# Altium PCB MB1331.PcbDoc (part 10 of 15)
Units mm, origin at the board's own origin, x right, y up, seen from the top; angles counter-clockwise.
Board outline 169.25 x 173.25 mm, 6 copper layers (Top Layer, Signal Layer 1, Signal Layer 2, Signal Layer 3, Signal Layer 4, Bottom Layer), stack 1.556 mm thick; 871 components, 699 nets, 3244 pads, 2370 vias.
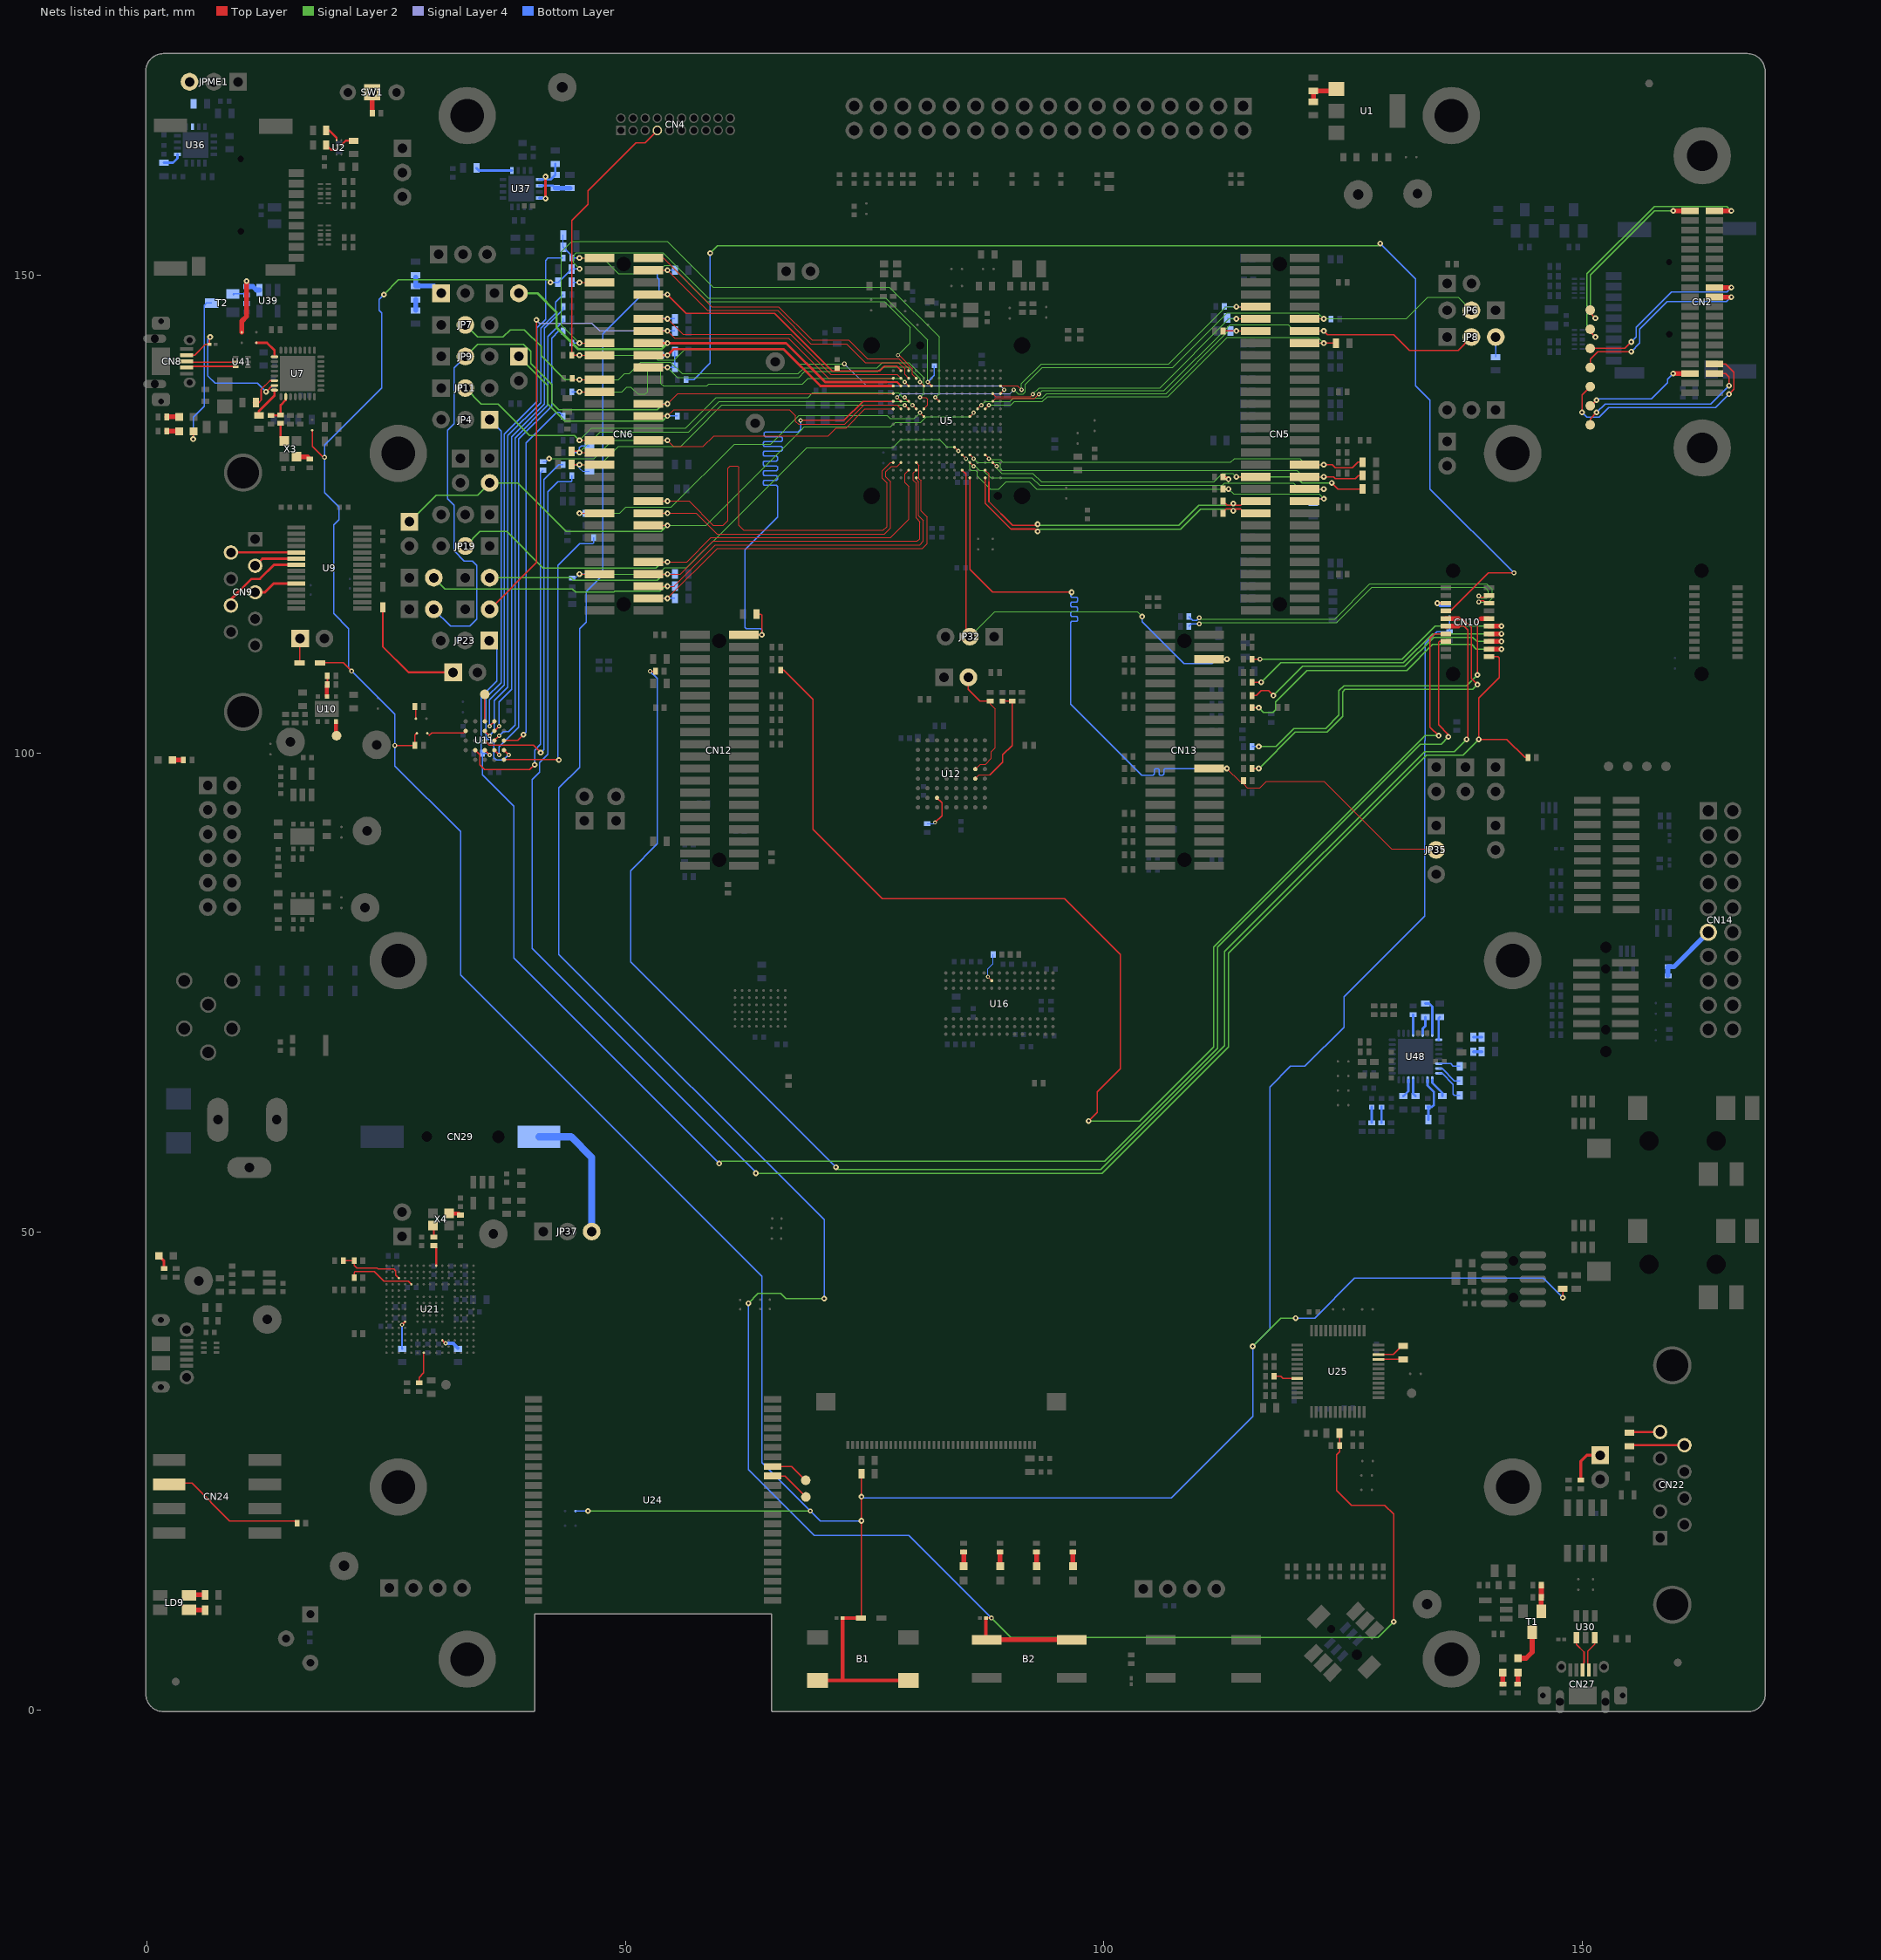
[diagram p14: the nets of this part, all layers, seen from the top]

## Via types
v1: diameter 0.6, hole 0.254, Top Layer to Bottom Layer, tented both sides, 1747 vias
v2: diameter 0.45, hole 0.2, Top Layer to Bottom Layer, tented both sides, 272 vias
v3: diameter 0.406, hole 0.203, Top Layer to Bottom Layer, tented both sides, 160 vias
v4: diameter 0.6, hole 0.25, Top Layer to Bottom Layer, tented both sides, 82 vias
v5: diameter 0.45, hole 0.25, Top Layer to Bottom Layer, tented both sides, 45 vias
v6: diameter 0.5, hole 0.25, Top Layer to Bottom Layer, tented both sides, 23 vias
v7: diameter 1.016, hole 0.508, Top Layer to Bottom Layer, tented both sides, 17 vias
v8: diameter 0.508, hole 0.254, Top Layer to Bottom Layer, tented both sides, 9 vias
v9: diameter 0.61, hole 0.305, Top Layer to Bottom Layer, tented both sides, 7 vias
v10: diameter 0.5, hole 0.254, Top Layer to Bottom Layer, tented both sides, 6 vias
v11: diameter 0.4, hole 0.2, Top Layer to Bottom Layer, tented both sides, 1 vias
v12: diameter 0.483, hole 0.254, Top Layer to Bottom Layer, tented both sides, 1 vias

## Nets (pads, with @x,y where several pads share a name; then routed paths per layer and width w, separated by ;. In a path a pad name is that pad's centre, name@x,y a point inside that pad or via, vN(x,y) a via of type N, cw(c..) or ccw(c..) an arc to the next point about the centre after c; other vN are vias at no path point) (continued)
NetC147_2: C147.2 U48.9 | length 2.4
  Bottom Layer w0.254: U48.9@135.013,70.076 135.013,72.337 C147.2@135.128,72.452
NetC148_1: C148.1 U48.8 | length 3.7
  Bottom Layer w0.254: C148.1@133.638,73.886 C148.1@133.604,73.852 134.019,73.852 134.338,73.533 U48.8@134.338,70.751
NetC148_2: C148.2 U48.6 | length 1.8
  Bottom Layer w0.254: U48.6@133.338,70.751 133.338,71.247 133.604,71.513 C148.2@133.604,72.452
NetC151_1: C151.1 R410.2 | length 0.9
  Bottom Layer w0.3: C151.1@138.622,70.358 R410.2@139.508,70.358
NetC159_1: C159.1 R412.2 | length 0.9
  Bottom Layer w0.3: C159.1@138.622,68.834 R412.2@139.508,68.834
NetC160_2: C160.2 U48.14 | length 2.3
  Bottom Layer w0.127: U48.14@135.013,67.576 136.259,67.576 136.525,67.31 C160.2@137.222,67.31
NetC161_2: C161.2 U48.15 | length 2.7
  Bottom Layer w0.127: U48.15@135.013,67.076 135.362,67.076 136.652,65.786 C161.2@137.222,65.786
NetC163_2: C163.2 U48.16 | length 3.8
  Bottom Layer w0.127: U48.16@135.013,66.576 135.354,66.576 136.525,65.405 136.525,64.389 136.652,64.262 C163.2@137.222,64.262
NetC164_2: C164.2 U48.17 | length 2.1
  Bottom Layer w0.254: U48.17@134.338,65.901 134.338,65.56 135.382,64.516 C164.2@135.382,64.2
NetC165_1: C165.1 U48.21 | length 1.8
  Bottom Layer w0.254: U48.21@132.338,65.901 132.338,64.45 C165.1@132.588,64.2
NetC166_1: C166.1 U48.22 | length 1.9
  Bottom Layer w0.254: C166.1@131.318,64.2 131.838,64.72 U48.22@131.838,65.901
NetC167_1: C167.1 R415.2 U48.18 | length 5
  Bottom Layer w0.254: U48.18@133.838,65.901 133.838,65.298 134.493,64.643 134.493,63.246 134.297,63.05 C167.1@133.858,63.05 133.92,62.988 R415.2@133.92,61.722
NetC169_1: C169.1 R417.2 | length 1.6
  Bottom Layer w0.254: R417.2@129.032,61.41 C169.1@129.032,63.05
NetC170_1: C170.1 R418.2 | length 1.6
  Bottom Layer w0.254: R418.2@128.016,61.41 C170.1@128.016,63.05
NetC187_2: C187.2 U21.F13 | length 2
  Top Layer w0.2: U21.F13@30.875,38.675 v2(31.2,38.35)
  Bottom Layer w0.381: v2(31.2,38.35) 32,38.35 C187.2@32.495,37.855
NetC188_2: C188.2 U21.M10 | length 3
  Top Layer w0.2: v2(26.65,40.3) U21.M10@26.975,40.625
  Bottom Layer w0.203: v2(26.65,40.3) 26.65,37.804 C188.2@26.67,37.784
NetCN2_1: CN2.1 TP2.1 | length 19
  Top Layer w0.127: TP2.1@150.846,146.327 150.846,146.016 v1(151.384,145.478)
  Top Layer w0.508: v1(159.513,156.685) CN2.1@161.28,156.685
  Signal Layer 2 w0.127: v1(151.384,145.478) 150.876,145.987 150.876,149.987 157.574,156.685 v1(159.513,156.685)
NetCN2_2: CN2.2 TP3.1 | length 28
  Top Layer w0.127: TP3.1@150.846,144.327 150.846,144.048 v1(151.384,143.51)
  Top Layer w0.508: CN2.2@163.83,156.685 v1(165.597,156.685)
  Signal Layer 2 w0.127: v1(151.384,143.51) 150.495,144.399 150.495,150.114 157.543,157.162 165.119,157.162 v1(165.597,156.685)
NetCN2_18: CN2.18 TP4.1 | length 19.7
  Top Layer w0.127: TP4.1@150.846,142.327 154.456,142.327 v1(155.13,143.002)
  Top Layer w0.508: CN2.18@163.83,148.685 v1(165.597,148.685)
  Bottom Layer w0.127: v1(155.13,143.002) 155.638,143.51 155.638,144.526 159.321,148.209 165.121,148.209 v1(165.597,148.685)
NetCN2_20: CN2.20 TP5.1 | length 20.9
  Top Layer w0.127: TP5.1@150.846,140.327 150.846,141.194 151.638,141.986 v1(155.13,141.986)
  Top Layer w0.508: CN2.20@163.83,147.685 v1(165.597,147.685)
  Bottom Layer w0.127: v1(155.13,141.986) 156.019,142.875 156.019,144.335 158.877,147.193 165.105,147.193 v1(165.597,147.685)
NetCN2_34: CN2.34 TP6.1 | length 24.5
  Top Layer w0.127: v1(149.987,135.636) 149.987,137.468 TP6.1@150.846,138.327 ; CN2.34@163.83,140.685 165.004,140.685 165.862,139.827 165.862,138.049 v1(165.354,137.541)
  Bottom Layer w0.127: v1(149.987,135.636) 150.495,135.128 151.765,135.128 152.781,136.144 163.957,136.144 v1(165.354,137.541)
NetCN2_35: CN2.35 TP7.1 | length 12
  Top Layer w0.127: TP7.1@150.846,136.327 150.932,136.327 v1(151.511,136.906)
  Top Layer w0.508: v1(159.512,139.685) CN2.35@161.28,139.685
  Bottom Layer w0.127: v1(151.511,136.906) 151.638,137.033 157.226,137.033 158.943,138.75 158.943,139.116 v1(159.512,139.685)
NetCN2_36: CN2.36 TP8.1 | length 19.1
  Top Layer w0.127: TP8.1@150.846,134.327 150.846,134.971 v1(151.511,135.636) ; CN2.36@163.83,139.685 164.988,139.685 165.354,139.319 v1(165.354,138.43)
  Bottom Layer w0.127: v1(151.511,135.636) 152.4,136.525 163.449,136.525 v1(165.354,138.43)
NetCN7_1: CN7.1 R221.2 R222.1 | length 4.1
  Bottom Layer w0.127: R221.2@28.08,149.774 R221.2@28.08,149.974
  Bottom Layer w0.5: R221.2@28.08,149.774 R222.1@28.08,148.834 29.982,148.834 CN7.1@30.734,148.082
NetCN8_2: CN8.2 U41.6 | length 5.2
  Top Layer w0.155: CN8.2@4.13,140.32 4.26,140.45 9.218,140.45 U41.6@9.256,140.412
NetCN8_3: CN8.3 U41.5 | length 5.2
  Top Layer w0.155: CN8.3@4.13,140.97 4.225,140.875 9.219,140.875 U41.5@9.256,140.912
NetCN8_4: CN8.4 U6.1 U7.23 | length 15.8
  Top Layer w0.155: CN8.4@4.13,141.62 4.968,141.62 6.096,142.748 U6.1@6.546,142.748 6.546,143.452 v1(6.604,143.51) ; v1(12.446,137.795) 13.101,138.45 U7.23@13.323,138.45
  Bottom Layer w0.155: v1(6.604,143.51) 6.35,143.256 6.35,139.446 7.112,138.684 11.557,138.684 v1(12.446,137.795)
NetCN9_2: CN9.2 U9.6 | length 5.1
  Top Layer w0.254: CN9.2@11.835,119.61 CN9.2@11.31,119.61 12.055,120.355 U9.6@15.6,120.355
NetCN9_3: CN9.3 U9.10 | length 4.7
  Top Layer w0.254: CN9.3@11.31,116.84 12.319,116.84 13.234,117.755 U9.10@15.6,117.755
NetCN9_6: CN9.6 U9.5 | length 6.8
  Top Layer w0.254: CN9.6@8.77,120.995 8.78,121.005 U9.5@15.6,121.005
NetCN9_8: CN9.8 U9.7 | length 9
  Top Layer w0.254: CN9.8@8.77,115.455 8.77,116.085 10.922,118.237 11.811,118.237 13.279,119.705 U9.7@15.6,119.705
NetCN14_11: CN14.11 R395.2 R396.1 | length 6.6
  Bottom Layer w0.508: R396.1@158.95,76.8 158.95,77.65 R395.2@159,77.7 159.58,77.7 CN14.11@163.195,81.315
NetCN22_5: CN22.5 R169.2 | length 3.2
  Top Layer w0.254: R169.2@154.94,29.018 155.018,29.096 CN22.5@158.155,29.096
NetCN22_9: CN22.9 R174.2 | length 5.8
  Top Layer w0.254: R174.2@154.94,27.624 155.027,27.711 CN22.9@160.695,27.711
NetCN24_5: CN24.5 R177.1 | length 15
  Top Layer w0.127: CN24.5@2.413,23.749 4.699,23.749 8.636,19.812 15.425,19.812 R177.1@15.679,19.558
NetCN27_2: CN27.2 U30.6 | length 3.7
  Top Layer w0.155: CN27.2@150.705,4.23 150.705,4.743 150.59,4.858 150.59,6.191 151.318,6.919 U30.6@151.318,7.588
NetCN27_3: CN27.3 U30.4 | length 3.7
  Top Layer w0.155: U30.4@149.418,7.588 149.418,6.887 150.209,6.096 150.209,4.972 150.055,4.818 CN27.3@150.055,4.23
NetCN29_1: CN29.1 JP37.3 | length 14.2
  Bottom Layer w0.762: CN29.1@40.966,59.944 44.323,59.944 46.482,57.785 JP37.3@46.482,50.038
NetD1_2: D1.2 JP22.1 | length 12.6
  Top Layer w0.2: D1.2@24.638,115.262 24.638,111.162 27.332,108.468 JP22.1@32.005,108.468
NetD2_2: D2.2 JP24.1 | length 2.6
  Top Layer w0.127: D2.2@15.948,109.474 15.948,111.96 JP24.1@16.002,112.014
NetJP38_1: JP38.1 R176.2 | length 4.3
  Top Layer w0.3: R176.2@149.86,24.072 149.86,26.035 150.495,26.67 JP38.1@151.892,26.67
NetJPME1_3: JPME1.3 R197.2 U36.6
NetLD1_2: LD1.2 R178.1 | length 1.5
  Top Layer w0.508: R178.1@85.344,16.568 85.36,16.552 LD1.2@85.36,15.082
NetLD2_2: LD2.2 R179.1 | length 1.5
  Top Layer w0.508: R179.1@89.154,16.568 89.17,16.552 LD2.2@89.17,15.082
NetLD3_2: LD3.2 R180.1 | length 1.5
  Top Layer w0.508: R180.1@92.964,16.568 92.98,16.552 LD3.2@92.98,15.082
NetLD4_2: LD4.2 R181.1 | length 1.5
  Top Layer w0.508: R181.1@96.774,16.568 96.774,15.098 LD4.2@96.79,15.082
NetLD5_1: LD5.1 R42.1 | length 1.3
  Top Layer w0.508: R42.1@2.065,135.165 LD5.1@3.365,135.165
NetLD6_1: LD6.1 R46.1 | length 1.3
  Top Layer w0.508: R46.1@2.065,133.665 LD6.1@3.365,133.665
NetLD6_2: LD6.2 T2.3 | length 16.1
  Top Layer w0.127: v1@4.865,132.881 LD6.2@4.865,133.665
  Bottom Layer w0.127: v1(4.826,132.842) 4.826,135.128 5.969,136.271 5.969,146.812 6.223,147.066 T2.3@6.774,147.066
NetLD7_1: LD7.1 R112.2 | length 1.2
  Top Layer w0.508: LD7.1@2.655,99.314 R112.2@3.81,99.314
NetLD8_1: LD8.1 R149.1 | length 1.5
  Top Layer w0.3: LD8.1@1.25,47.5 1.778,46.972 R149.1@1.778,46.17
NetLD9_2: LD9.2 R190.1 | length 1.7
  Top Layer w0.508: LD9.2@4.377,12.028 4.427,12.078 R190.1@6.077,12.078
NetLD9_3: LD9.3 R192.1 | length 1.7
  Top Layer w0.508: LD9.3@4.377,10.528 4.427,10.478 R192.1@6.077,10.478
NetLD10_1: LD10.1 R195.1 | length 1.2
  Top Layer w0.254: R195.1@141.697,2.771 R195.1@141.732,2.736
  Top Layer w0.508: R195.1@141.697,2.771 LD10.1@141.697,3.955
NetLD11_1: LD11.1 R196.1 | length 1.2
  Top Layer w0.254: R196.1@143.256,2.736 R196.1@143.297,2.777
  Top Layer w0.508: R196.1@143.297,2.777 LD11.1@143.297,3.955
NetLD11_2: LD11.2 T1.3 | length 3.8
  Top Layer w0.508: LD11.2@143.297,5.455 144.139,5.455 144.78,6.096 T1.3@144.78,8.171
NetR1_2: R1.2 R2.2 U1.1 | length 3.6
  Top Layer w0.508: R2.2@121.92,168.086 R1.2@121.92,169.226 124.127,169.226 U1.1@124.333,169.432
NetR3_2: R3.2 SW1.1 | length 2.2
  Top Layer w0.508: SW1.1@23.538,169.075 23.55,169.063 R3.2@23.55,166.9
NetR4_2: R4.2 U2.1 | length 1.7
  Top Layer w0.203: R4.2@18.734,165.1 19.05,165.1 19.816,164.334 U2.1@19.816,164.072
NetR5_1: R5.1 U2.7 | length 1.5
  Top Layer w0.203: U2.7@20.316,163.572 20.766,164.022 R5.1@21.59,164.022
NetR6_2: R6.2 U2.3 | length 1.3
  Top Layer w0.203: R6.2@18.734,163.576 19.238,163.072 U2.3@19.816,163.072
NetR36_1: R36.1 U7.22 | length 3.8
  Top Layer w0.152: R36.1@11.114,136.652 R36.1@11.368,136.652 11.684,136.652 11.938,136.906 11.938,138.049 12.839,138.95 U7.22@13.323,138.95
NetR37_1: R37.1 U7.24 | length 3.5
  Top Layer w0.254: R37.1@11.684,135.32 11.684,135.763 13.323,137.402 U7.24@13.323,137.95 U7.24@13.109,137.95
NetR38_1: R38.1 X3.3 | length 2
  Top Layer w0.254: R38.1@13.97,134.482 13.97,133.042 X3.3@14.361,132.651
NetR38_2: R38.2 R39.2 U7.26 | length 3.2
  Top Layer w0.254: R39.2@12.954,135.324 13.912,135.324 R38.2@13.97,135.382 13.97,136.398 14.498,136.926 U7.26@14.498,137.275
NetR52_2: R52.2 X3.1 | length 1.7
  Top Layer w0.508: X3.1@15.744,130.868 X3.1@15.611,131.001 16.769,131.001 R52.2@17.018,130.752
NetR83_2: R83.2 R90.2 U10.5 | length 2.2
  Top Layer w0.203: R90.2@18.85,108.1 18.85,107.192 R83.2@18.854,107.188
  Top Layer w0.381: U10.5@18.796,105.948 18.796,107.13 R83.2@18.854,107.188
NetR94_1: R94.1 SB20.2 | length 1.3
  Top Layer w0.127: R94.1@27.998,104.902 28.102,104.798 SB20.2@28.102,103.632
NetR144_2: R144.2 X4.1 | length 1.3
  Top Layer w0.4: X4.1@31.559,51.933 32.591,51.933 R144.2@32.766,51.758
NetR145_1: R145.1 X4.3 | length 1.2
  Top Layer w0.203: X4.3@29.909,50.683 29.972,50.62 R145.1@29.972,49.472
NetR145_2: R145.2 U21.G1 | length 2.2
  Top Layer w0.203: R145.2@29.972,48.572 30.225,48.319 U21.G1@30.225,46.475
NetR146_1: R146.1 R147.1 U21.N3 | length 7.1
  Top Layer w0.127: R146.1@20.516,46.99 R147.1@21.648,46.99 21.648,46.507 21.927,46.228 24.037,46.228 24.151,46.114 25.794,46.114 26,45.908 26,45.5 U21.N3@26.325,45.175
NetR151_2: R151.2 U21.L4 | length 7.1
  Top Layer w0.127: R151.2@21.648,45.212 21.648,45.778 21.717,45.847 23.749,45.847 24.746,44.85 27.3,44.85 U21.L4@27.625,44.525
NetR158_1: R158.1 U25.21 | length 2.6
  Top Layer w0.127: U25.21@128.71,36.683 131.267,36.683 R158.1@131.275,36.675
NetR158_2: R158.2 U25.22 | length 2.9
  Top Layer w0.127: U25.22@128.71,37.183 130.258,37.183 131.15,38.075 R158.2@131.275,38.075
NetR163_1: R163.1 U25.44 | length 2.5
  Top Layer w0.127: R163.1@117.798,34.925 118.491,34.925 118.733,34.683 U25.44@120.21,34.683
NetR165_2: R165.2 U21.J15 | length 3.3
  Top Layer w0.127: R165.2@28.448,34.232 28.448,34.798 28.925,35.275 U21.J15@28.925,37.375
NetR189_2: R189.2 R191.2 T1.1 | length 2.7
  Top Layer w0.508: T1.1@145.73,10.371 145.73,11.803 R191.2@145.738,11.811 R189.2@145.738,13.081
NetR200_2: R200.2 R204.1 U37.5 U37.8 | length 6.2
  Top Layer w0.254: v1(41.656,157.988) v1(41.656,160.274)
  Bottom Layer w0.254: U37.8@41.016,158.029 41.615,158.029 v1(41.656,157.988) ; U37.5@41.016,159.979 v1@41.656,159.979 ; v1(41.656,160.274) v1@41.656,159.979 ; R200.2@42.672,161.606 R204.1@42.672,160.466 42.185,159.979 v1@41.656,159.979
NetR201_1: R201.1 U37.1 | length 3.8
  Bottom Layer w0.254: R201.1@34.438,161.163 34.697,160.904 U37.1@38.141,160.904
NetR202_1: R202.1 U36.1 | length 2
  Bottom Layer w0.254: R202.1@1.778,161.736 2.732,161.736 3.18,162.184 U36.1@3.18,162.601
NetR203_1: R203.1 R204.2 U37.6 | length 3.3
  Bottom Layer w0.254: U37.6@41.016,159.329 42.409,159.329 R204.2@42.672,159.066
  Bottom Layer w0.508: R204.2@42.672,159.066 R203.1@44.196,159.066
NetR222_2: R222.2 R223.1 | length 1.1
  Bottom Layer w0.5: R223.1@28.08,146.294 R222.2@28.08,147.434
NetR228_1: R228.1 SB11.1 U39.1 | length 7.6
  Top Layer w0.508: SB11.1@9.906,144.01 9.906,145.161 10.414,145.669 v1(10.414,149.352)
  Bottom Layer w0.508: v1(10.414,149.352) R228.1@10.414,148.786 11.064,148.786 11.43,148.42 U39.1@11.75,148.42
NetR228_2: R228.2 R232.2 T2.1 | length 2.6
  Bottom Layer w0.127: T2.1@9.104,147.886 T2.1@8.974,148.016 10.284,148.016 R228.2@10.414,147.886 R232.2@10.414,147.008
NetR376_1: R376.1 U12.F7 | length 4
  Top Layer w0.127: v3(82.366,92.786) 83.077,93.497 83.077,94.857 U12.F7@82.567,95.366
  Bottom Layer w0.102: R376.1@81.534,92.652 82.231,92.652 v3(82.366,92.786)
NetR397_2: R397.2 U16.J2 | length 3.1
  Top Layer w0.102: v3(87.896,76.663) U16.J2@88.297,76.263
  Bottom Layer w0.102: v3(87.896,76.663) 87.896,77.482 88.45,78.036 R397.2@88.45,78.994
NetR402_1: R402.1 U48.4 | length 2
  Bottom Layer w0.254: R402.1@132.334,72.702 132.334,71.251 132.338,71.247 U48.4@132.338,70.751
NetSB12_2: SB12.2 U7.17 | length 2.9
  Top Layer w0.254: SB12.2@11.43,142.91 12.538,142.91 13.323,142.125 U7.17@13.323,141.45
NetTP9_1: TP9.1 U11.C5 | length 2.8
  Top Layer w0.127: U11.C5@35.306,103.346 TP9.1@35.306,106.172
NetTP11_1: TP11.1 U10.3 | length 1.5
  Top Layer w0.381: U10.3@19.746,103.348 19.746,101.92 TP11.1@19.812,101.854
NetTP26_1: TP26.1 U24.36 | length 4.4
  Top Layer w0.127: U24.36@65.4,24.5 66.672,24.5 TP26.1@68.868,22.304
NetTP27_1: TP27.1 U24.37 | length 4
  Top Layer w0.127: U24.37@65.4,25.5 67.39,25.5 TP27.1@68.841,24.048
NJTRST: JP8.3 R252.2 | length 2.1
  Bottom Layer w0.127: R252.2@140.97,141.416 JP8.3@140.97,143.51
NOR_NRST: C43.1 R85.2 U12.B5 | length 11.4
  Top Layer w0.102: U12.B5@86.568,97.366 86.966,97.765 88.106,97.765
  Top Layer w0.127: 88.106,97.765 89.452,99.111 89.452,99.866 90.424,100.838 R85.2@90.424,105.468 C43.1@89.408,105.468
NOR_NWP: JP25.2 R84.1 U12.B4 | length 12.6
  Top Layer w0.102: U12.B4@86.568,98.366 87.083,98.882 87.649,98.882 88.265,99.499 88.265,100.203 88.646,100.584 88.646,104.648 88.138,105.156 R84.1@88.138,105.468
  Top Layer w0.127: JP25.2@85.852,107.95 85.852,106.68 87.064,105.468 R84.1@88.138,105.468
NRST: B1.3 B1.4 C107.2 D2.1 D3.2 R106.2 R125.1 R155.1 R218.2 R225.1 R321.2 SB13.2 SB21.1 SB38.1 SB45.2 U5.K3 U31.1 | length 472.3
  Top Layer w0.127: SB13.2@17.272,133.766 17.272,132.08 18.415,130.937 v6(18.542,130.937) ; D2.1@18.088,109.474 20.526,109.474 v6(21.4,108.6) ; v6(25.908,100.838) R106.2@27.998,100.838 27.998,101.904 SB21.1@28.202,102.108 ; D3.2@74.622,9.652 74.675,9.705 v1(74.675,19.812) v1(74.675,22.325) R125.1@74.675,24.725 ; v1(147.975,43.125) R155.1@147.975,44.075 ; v2(81.6,138.8) U5.K3@82,138.4 v2(81.6,138.8)
  Top Layer w0.381: B1.3@70.093,3.137 72.771,3.137 ; D3.2@74.368,9.652 U31.1@72.702,9.652 72.702,3.206 72.771,3.137 ; B1.4@79.593,3.137 72.771,3.137
  Signal Layer 2 w0.1: v4(45.212,150.622) 44.577,151.257 44.577,152.019 44.858,152.3 53.948,152.3 58.674,147.574 77.216,147.574 81.6,143.19 v2(81.6,138.8)
  Signal Layer 2 w0.127: v4(24.765,147.955) 26.285,149.475 41.914,149.475 v1(42.164,149.225) ; v4(46.101,20.828) v6(69.342,20.828) ; v1(115.57,38.045) 118.525,41 v1(120.05,41)
  Bottom Layer w0.127: v4(24.765,147.955) 24.257,147.447 24.257,146.304 24.511,146.05 24.511,138.176 18.542,132.207 v6(18.542,130.937) 18.542,127.258 20.07,125.73 20.07,124.43 19.5,123.86 19.5,114.612 21.082,113.03 21.082,108.918 v6(21.4,108.6) 22.34,107.66 25.908,104.092 v6(25.908,100.838) 25.908,98.679 32.766,91.821 32.766,76.835 64.262,45.339 64.262,25.908 v6(69.342,20.828) 70.358,19.812 v1(74.675,19.812) ; v1(42.164,149.225) R225.1@42.988,149.225 44.385,150.622 R218.2@44.388,150.622 v4(45.212,150.622) ; SB45.2@44.796,20.828 v4(46.101,20.828) ; v1(74.675,22.325) 74.775,22.225 107.061,22.225 115.57,30.734 v1(115.57,38.045) 117.348,39.823 117.348,65.151 119.507,67.31 121.031,67.31 125.095,71.374 125.095,74.549 133.559,83.013 133.559,101.33 133.604,101.376 133.604,111.506 134.816,112.718 R321.2@136.144,112.718 SB38.1@136.144,114.308 ; v2(81.6,138.8) 82.296,139.496 C107.2@82.296,140.52 ; v1(120.05,41) 122.05,41 126.225,45.175 145.925,45.175 v1(147.975,43.125)
NRST_E: CN6.5 R225.2 | length 2.9
  Top Layer w0.1: v1(45.2,149.225) CN6.5@47.293,149.225
  Bottom Layer w0.127: R225.2@44.388,149.225 v1(45.2,149.225)
OCSPI1_CLK: R283.1 U11.B2 | length 39
  Top Layer w0.127: U11.B2@34.306,100.346 34.798,99.854 34.798,98.806 35.306,98.298 40.005,98.298 v1(40.513,98.806)
  Bottom Layer w0.127: v1(40.513,98.806) 40.513,100.33 41.125,100.942 41.125,129.321 R283.1@41.402,129.598
OCSPI1_DQS: R286.1 U11.C3 | length 37.7
  Top Layer w0.127: U11.C3@35.306,101.346 35.8,100.852 40.372,100.852 v1(41.148,100.076)
  Bottom Layer w0.127: v1(41.148,100.076) 41.5,100.428 41.5,128.622 43.053,130.175 R286.1@43.492,130.175
OCSPI1_IO0: R237.2 U11.D3 | length 47.4
  Top Layer w0.127: U11.D3@36.306,101.346 v2(36.8,101.84)
  Bottom Layer w0.127: v2(36.8,101.84) 37.26,102.3 37.809,102.3 38.481,102.972 38.481,132.969 41.91,136.398 41.91,143.566 43.492,145.148 R237.2@43.492,145.415
OCSPI1_IO1: R241.2 U11.D2 | length 48
  Top Layer w0.127: U11.D2@36.306,100.346 v2(36.8,99.852)
  Bottom Layer w0.127: v2(36.8,99.852) 36.8,100.681 38.862,102.743 38.862,132.842 42.291,136.271 42.291,143.383 43.053,144.145 R241.2@43.492,144.145
OCSPI1_IO2: R230.2 U11.C4 | length 50
  Top Layer w0.127: U11.C4@35.306,102.346 v2(35.8,101.852)
  Bottom Layer w0.127: v2(35.8,101.852) 36.3,102.352 36.3,105.5 37.719,106.919 37.719,133.223 41.148,136.652 41.148,144.448 42.7,146 42.7,147.163 R230.2@43.492,147.955
OCSPI1_IO3: R234.2 U11.D4 | length 47.3
  Top Layer w0.127: U11.D4@36.306,102.346 v2(36.8,102.84)
  Bottom Layer w0.127: v2(36.8,102.84) 36.8,105.4 38.1,106.7 38.1,133.096 41.529,136.525 41.529,144.429 43.492,146.392 R234.2@43.492,146.685
OCSPI1_IO4: R216.1 U11.D5 | length 53.7
  Top Layer w0.127: v2(35.812,102.852) U11.D5@36.306,103.346
  Bottom Layer w0.127: v2(35.812,102.852) 35.812,105.612 37.338,107.138 37.338,133.35 40.767,136.779 40.767,144.467 41.656,145.356 41.656,151.511 41.91,151.765 R216.1@43.492,151.765
OCSPI1_IO5: R272.1 U11.E3 | length 38.3
  Top Layer w0.127: U11.E3@37.306,101.346 38.735,101.346 v1(39.345,101.956)
  Bottom Layer w0.127: v1(39.345,101.956) 39.624,102.235 39.624,132.461 42.799,135.636 43.111,135.636 R272.1@43.492,135.255
OCSPI1_IO6: JP4.1 U11.E2 | length 39.6
  Top Layer w0.127: U11.E2@37.306,100.346 v2(37.8,99.852)
  Bottom Layer w0.127: JP4.1@35.815,134.875 37.002,133.688 37.002,107.403 35.411,105.812 35.411,101.691 35.639,101.464 35.892,101.464 36.264,101.092 36.264,99.536 36.5,99.3 37.248,99.3 v2(37.8,99.852)
OCSPI1_IO7: R300.1 U11.E1 | length 31.4
  Top Layer w0.127: U11.E1@37.306,99.346 43.021,99.346 v1(43.053,99.314)
  Bottom Layer w0.127: v1(43.053,99.314) 42.95,99.417 42.95,119.658 45.212,121.92 46.609,121.92 46.678,121.989 R300.1@46.678,122.555
OCSPI1_NCS: CN10.6 JP23.1 R355.2 U11.C2 | length 179.4
  Top Layer w0.127: U11.C2@35.306,100.346 v2(35.8,99.852) ; CN10.6@135.75,111.7 135.068,111.7 135.001,111.633 135.001,102.997 136.017,101.981 v1(136.017,101.727)
  Signal Layer 2 w0.127: v1(59.817,57.15) 60.071,57.404 100.076,57.404 111.887,69.215 111.887,79.756 133.096,100.965 135.255,100.965 v1(136.017,101.727)
  Bottom Layer w0.127: v2(35.8,99.852) 35.634,100.018 R355.2@35.063,100.018 ; JP23.1@35.815,111.76 36.576,110.999 36.576,107.576 34.925,105.925 34.925,100.145 35.052,100.018 R355.2@35.063,100.018 ; v1(59.817,57.15) 38.354,78.613 38.354,94.488 35.063,97.779 R355.2@35.063,100.018
OCSPI1_RESET: SB21.2 U11.A4 | length 4
  Top Layer w0.127: 29.464,101.854 29.765,102.155 33.115,102.155 U11.A4@33.306,102.346
OCSPI2_CLK_N: CN10.15 R318.1 | length 37.5
  Top Layer w0.13: v10(139.192,115.824) 139.319,115.951 139.7,115.951 139.951,115.7 CN10.15@140.25,115.7
  Signal Layer 2 w0.104: v10(109.982,114.173) 110.109,114.046 124.142,114.046 127.825,117.729 140.017,117.729 140.589,117.157 140.589,116.205 140.208,115.824 v10(139.192,115.824)
  Bottom Layer w0.13: R318.1@108.908,114.3 109.289,113.919 109.728,113.919 v10(109.982,114.173)
OCSPI2_CLK_P: CN10.17 R319.1 | length 36.1
  Top Layer w0.13: v10(139.192,116.459) 139.319,116.332 140.082,116.332 CN10.17@140.25,116.5
  Signal Layer 2 w0.104: v10(109.982,113.538) 110.109,113.665 124.333,113.665 128.016,117.348 139.827,117.348 140.208,116.967 140.208,116.395 140.017,116.205 139.446,116.205 v10(139.192,116.459)
  Bottom Layer w0.13: R319.1@108.908,113.284 109.162,113.538 v10(109.982,113.538)
OCSPI2_DQS: CN10.11 R354.1 | length 35
  Top Layer w0.127: v1(139.065,108.204) 139.065,113.719 139.446,114.1
  Top Layer w0.508: 139.446,114.1 CN10.11@140.25,114.1
  Signal Layer 2 w0.127: v1(116.205,100.711) 117.983,100.711 119.888,102.616 123.19,102.616 124.587,104.013 124.587,106.553 125.095,107.061 137.922,107.061 v1(139.065,108.204)
  Bottom Layer w0.127: R354.1@115.512,100.711 v1(116.205,100.711)
OCSPI2_IO0: CN10.3 R98.1 | length 31.2
  Top Layer w0.127: R98.1@115.512,104.775 v1(116.205,104.775)
  Top Layer w0.508: CN10.3@140.25,110.9 v1(141.562,110.9)
  Signal Layer 2 w0.127: v1(116.205,104.775) 116.68,104.3 117.7,104.3 117.973,104.573 117.973,105.4 121.245,108.672 131.659,108.672 134.366,111.379 138.459,111.379 138.938,110.9 v1(141.562,110.9)
OCSPI2_IO1: CN10.5 R89.1 | length 30.5
  Top Layer w0.127: R89.1@115.512,106.045 115.951,106.045 116.459,106.553 117.221,106.553 v1(117.729,106.045)
  Top Layer w0.508: CN10.5@140.25,111.7 v1(141.562,111.7)
  Signal Layer 2 w0.127: v1(117.729,106.045) 120.777,109.093 131.445,109.093 134.493,112.141 138.557,112.141 138.998,111.7 v1(141.562,111.7)
OCSPI2_IO2: CN10.7 R82.1 | length 29.5
  Top Layer w0.127: R82.1@115.512,107.442 v1(116.459,107.442)
  Top Layer w0.508: CN10.7@140.25,112.5 v1(141.562,112.5)
  Signal Layer 2 w0.127: v1(116.459,107.442) 118.491,109.474 131.318,109.474 134.344,112.5 v1(141.562,112.5)
OCSPI2_IO3: CN10.9 R75.1 | length 28.8
  Top Layer w0.127: R75.1@115.512,109.855 v10(116.332,109.855)
  Top Layer w0.508: CN10.9@140.25,113.3 v1(141.562,113.3)
  Signal Layer 2 w0.127: v10(116.332,109.855) 131.191,109.855 134.636,113.3 v1(141.562,113.3)
OCSPI2_IO4: CN10.8 R76.1 | length 146.2
  Top Layer w0.127: R76.1@66.236,108.712 66.548,108.712 69.596,105.664 69.596,92.075 76.835,84.836 95.885,84.836 101.727,78.994 101.727,67.056 99.314,64.643 99.314,62.484 v1(98.425,61.595) ; v1(135.001,101.854) 134.112,102.743 134.112,112.014 134.598,112.5 CN10.8@135.75,112.5
  Signal Layer 2 w0.127: v1(98.425,61.595) 103.759,61.595 111.506,69.342 111.506,79.756 133.604,101.854 v1(135.001,101.854)
OCSPI2_IO5: CN10.10 R77.1 | length 167.1
  Top Layer w0.127: v5(52.578,108.585) R77.1@53.144,108.585 ; 137.062,113.3 137.652,113.3 138.049,112.903 138.049,101.6 v1(137.922,101.473)
  Top Layer w0.508: CN10.10@135.75,113.3 137.062,113.3
  Signal Layer 2 w0.127: v1(72.009,56.769) 72.263,56.515 99.695,56.515 112.649,69.469 112.649,79.311 133.541,100.203 136.652,100.203 v1(137.922,101.473)
  Bottom Layer w0.127: v5(52.578,108.585) 53.34,107.823 53.34,90.551 50.546,87.757 50.546,78.232 v1(72.009,56.769)
OCSPI2_IO6: CN10.12 R115.1 | length 38
  Top Layer w0.127: R115.1@115.512,98.425 v1(116.205,98.425) ; 137.062,114.1 137.487,114.1 138.43,113.157 138.43,107.823 v1(139.065,107.188)
  Top Layer w0.508: CN10.12@135.75,114.1 137.062,114.1
  Signal Layer 2 w0.127: v1(116.205,98.425) 120.015,102.235 123.317,102.235 124.968,103.886 124.968,106.426 125.222,106.68 138.557,106.68 v1(139.065,107.188)
OCSPI2_IO7: CN10.14 R257.1 | length 134.2
  Top Layer w0.127: CN10.14@135.75,114.9 136.236,114.9 140.208,118.872 v6(142.875,118.872)
  Signal Layer 2 w0.127: v4(58.864,152.273) 59.627,153.035 128.651,153.035 v1(128.905,153.289)
  Bottom Layer w0.127: R257.1@56.33,139.065 57.15,139.065 58.864,140.779 v4(58.864,152.273) ; v1(128.905,153.289) 132.588,149.606 132.588,138.43 134.112,136.906 134.112,127.635 v6(142.875,118.872)
OCSPI2_NCS: CN10.1 R111.2 R287.1 | length 201.7
  Top Layer w0.127: CN10.1@140.25,110.1 141.224,110.1 141.351,109.973 141.351,107.95 139.192,105.791 v1(139.192,101.473) 142.113,101.473 144.018,99.568 R111.2@144.33,99.568
  Signal Layer 2 w0.127: v1(63.627,56.134) 99.822,56.134 113.03,69.342 113.03,79.121 133.731,99.822 137.541,99.822 v1(139.192,101.473)
  Bottom Layer w0.127: R287.1@44.392,129.032 44.392,128.466 44.323,128.397 42.926,128.397 41.875,127.346 41.875,99.914 41.021,99.06 41.021,98.044 40.259,97.282 40.259,79.629 63.627,56.261 v1(63.627,56.134)
OCSPI2_RESET: CN10.16 SB38.2 | length 2.3
  Top Layer w0.254: v1(134.874,115.697) 134.877,115.7 CN10.16@135.75,115.7
  Bottom Layer w0.254: v1(134.874,115.697) 135.163,115.408 SB38.2@136.144,115.408
PA0: C30.1 CN6.8 R213.2 R229.2 U5.P1 | length 33.9
  Top Layer w0.1: CN6.8@52.393,147.955 v1(54.4,147.955)
  Top Layer w0.127: v1(54.4,147.955) 56.355,146 65.582,146 71.628,139.954 72.136,139.954 ; C30.1@72.136,140.266 72.136,139.954 ; U5.P1@78.8,140 78.338,140.462 77.089,140.462 76.581,139.954 72.136,139.954
  Bottom Layer w0.127: R213.2@53.34,150.43 53.34,149.733 53.536,149.537 R229.2@53.536,147.955 v1(54.4,147.955)
PA0_C: CN6.16 JP5.2 R244.2 U5.P3 | length 48
  Top Layer w0.2: 77.3,138.8 78.4,138.8 U5.P3@78.8,138.4
  Top Layer w0.254: CN6.16@52.393,142.875 v1(54.4,142.875) 66.802,142.875 70.877,138.8 77.3,138.8
  Signal Layer 2 w0.254: JP5.2@38.862,148.082 40.818,148.082 42.8,146.1 42.8,144.53 45.09,142.24 53.765,142.24 v1(54.4,142.875)
  Bottom Layer w0.254: R244.2@53.79,142.875 v1(54.4,142.875)
PA0_WAKEUP: B2.3 B2.4 R170.2 R172.2 R229.1 U32.1 | length 258.2
  Top Layer w0.127: U32.1@87.688,9.652 v6(88.265,9.652) ; R170.2@124.652,28.956 124.656,28.952 R172.2@124.656,27.686 124.656,27.025 124.356,26.725 124.356,22.969 125.9,21.425 129.375,21.425 130.302,20.498 v4(130.302,9.271)
  Top Layer w0.381: B2.4@87.688,7.454 U32.1@87.688,9.652
  Top Layer w0.508: B2.4@87.753,7.39 B2.3@96.653,7.39
  Signal Layer 2 w0.127: v4(62.865,42.545) 63.881,43.561 66.25,43.561 66.776,43.035 v4(70.775,43.035) ; v6(88.265,9.652) 90.297,7.62 128.651,7.62 v4(130.302,9.271)
  Bottom Layer w0.127: R229.1@52.636,147.955 51.74,147.955 47.625,143.84 47.625,118.618 45.925,116.918 45.925,113.725 45.212,113.012 45.212,98.552 43.053,96.393 43.053,78.994 70.775,51.272 v4(70.775,43.035) ; v4(62.865,42.545) 62.865,25.146 69.723,18.288 79.629,18.288 v6(88.265,9.652)
PA1: CN6.12 R235.2 R236.2 U5.P2 | length 30.6
  Top Layer w0.1: CN6.12@52.393,145.415 v1(54.4,145.415) 56.015,143.8 67.274,143.8 71.474,139.6 78.4,139.6 U5.P2@78.8,139.2
  Bottom Layer w0.127: R236.2@53.536,145.415 v1(54.4,145.415) R235.2@55.18,145.415
PA1_C: CN6.18 R250.2 U5.R3 | length 28.1
  Top Layer w0.254: CN6.18@52.393,141.605 v1(54.4,141.605) 55.047,142.252 66.536,142.252 70.388,138.4 U5.R3@78,138.4
  Bottom Layer w0.254: R250.2@53.79,141.605 v1(54.4,141.605)
PA2: CN6.14 JP40.2 R239.2 R240.2 U5.R2 | length 75.7
  Top Layer w0.1: CN6.14@52.393,144.145 v1(54.4,144.145) 55.145,143.4 67.039,143.4 71.239,139.2 U5.R2@78,139.2
  Top Layer w0.127: JP40.2@35.814,115.062 40.7,119.948 v1(40.7,145.3)
  Signal Layer 4 w0.127: v1(40.7,145.3) 41.048,144.952 46.513,144.952 47.32,144.145 v1(54.4,144.145)
  Bottom Layer w0.127: R240.2@53.536,144.145 v1(54.4,144.145) R239.2@55.18,144.145
PA3: CN6.26 JP9.2 JP39.2 R258.1 U5.R4 | length 89
  Top Layer w0.1: CN6.26@52.393,136.525 v1(54.4,136.525) 55.475,137.6 U5.R4@78,137.6
  Signal Layer 2 w0.127: JP9.2@33.274,141.478 34.544,142.748 39.352,142.748 40.1,142 40.1,140.748 42.291,138.557 42.291,136.652 43.053,135.89 53.34,135.89 53.975,136.525 v1(54.4,136.525)
  Bottom Layer w0.1: R258.1@53.55,136.5 R258.1@53.575,136.525
  Bottom Layer w0.127: JP39.2@29.972,115.062 31.734,113.3 33.735,113.3 34.462,114.028 34.462,119.638 34,120.1 33.159,120.1 32.086,121.174 32.086,125.914 31.4,126.6 31.4,133.775 32.086,134.461 32.086,140.29 JP9.2@33.274,141.478 ; R258.1@53.575,136.525 v1(54.4,136.525)
PA4: CN6.21 JP7.2 R108.2 U5.L6 | length 61.1
  Top Layer w0.1: R108.2@44.45,139.2 44.585,139.065 v1(45.2,139.065) CN6.21@47.293,139.065 ; v2(80.8,137.2) 81.4,137.2 81.6,137 81.6,136.4 U5.L6@81.2,136
  Signal Layer 2 w0.1: v1(45.2,139.065) 49.265,139.065 49.9,139.7 50.419,139.7 51.619,140.9 54.7,140.9 55.915,139.685 65.147,139.685 65.157,139.675 68.075,139.675 68.7,140.3 76.3,140.3 76.843,140.843 79.629,140.843 81.2,139.272 81.2,137.6 v2(80.8,137.2)
  Signal Layer 2 w0.127: JP7.2@33.274,144.78 34.544,143.51 37.211,143.51 37.973,144.272 39.428,144.272 41.2,142.5 41.2,141.553 43.688,139.065 v1(45.2,139.065)
PA5: CN6.31 JP11.2 U5.N5 | length 53.1
  Top Layer w0.1: v1(45.2,132.715) CN6.31@47.293,132.715 ; v2(79.2,137.2) U5.N5@79.6,136.8
  Signal Layer 2 w0.1: v1(45.2,132.715) 46.47,133.985 56.285,133.985 57.386,135.086 59.389,137.089 59.5,137.2 69.1,137.2 69.568,137.668 78.532,137.668 79,137.2 v2(79.2,137.2)
  Signal Layer 2 w0.127: JP11.2@33.274,138.176 34.925,136.525 36.703,136.525 40.005,133.223 44.692,133.223 v1(45.2,132.715)
PA6: CN5.12 JP6.2 R349.2 U5.P5 | length 69.7
  Top Layer w0.1: v2(78.4,137.2) U5.P5@78.8,136.8 ; CN5.12@120.972,145.415 v1(122.994,145.415)
  Signal Layer 2 w0.1: v2(90.6,138) 91.059,137.541 91.567,137.541 91.821,137.795 91.821,138.557 93.599,140.335 107.188,140.335 112.903,146.05 122.359,146.05 v1(122.994,145.415) 131.615,145.415 133.874,147.674 137.06,147.674 JP6.2@138.43,146.304
  Signal Layer 4 w0.1: v2(78.4,137.2) 78.8,137.6 90.2,137.6 v2(90.6,138)
  Bottom Layer w0.1: v1(122.994,145.415) 123.715,145.415 R349.2@123.8,145.5
PA7: CN12.2 R67.2 R322.2 U5.R5 | length 61.9
  Top Layer w0.127: CN12.2@62.373,112.395 v1(64.262,112.395) 64.262,114.427 64.135,114.554 R67.2@63.692,114.554 ; v2(68.326,134.8) 72.824,134.8 74.824,136.8 U5.R5@78,136.8
  Bottom Layer w0.127: R322.2@63.442,112.395 v1(64.262,112.395) 64.262,112.903 64.135,113.03 62.611,113.03 62.484,113.157 62.484,121.285 65.913,124.714 65.913,127.889 65.786,128.016 64.516,128.016 64.389,128.143 64.389,128.397 64.516,128.524 65.786,128.524 65.913,128.651 65.913,128.905 65.786,129.032 64.516,129.032 64.389,129.159 64.389,129.413 64.516,129.54 65.786,129.54 65.913,129.667 65.913,129.921 65.786,130.048 64.516,130.048 64.389,130.175 64.389,130.429 64.516,130.556 65.786,130.556 65.913,130.683 65.913,130.937 65.786,131.064 64.516,131.064 64.389,131.191 64.389,131.445 64.516,131.572 66.294,131.572 66.421,131.699 66.421,131.953 66.294,132.08 64.516,132.08 64.389,132.207 64.389,132.461 64.516,132.588 66.294,132.588 66.421,132.715 66.421,132.969 66.294,133.096 64.643,133.096 64.516,133.223 64.516,133.477 64.643,133.604 68.072,133.604 68.326,133.858 v2(68.326,134.8)
PA8: CN6.53 R301.2 R308.2 U5.G11 | length 50.8
  Top Layer w0.1: v1(45.2,118.745) CN6.53@47.293,118.745 ; U5.G11@84.4,132 v2(84.8,131.6)
  Signal Layer 2 w0.1: v1(45.2,118.745) 53.447,118.745 54.102,119.4 56.4,119.4 60.117,123.117 68.961,131.953 77.953,131.953 78.8,132.8 82.8,132.8 83.583,132.017 84.383,132.017 v2(84.8,131.6)
  Bottom Layer w0.1: R308.2@44.45,118.306 44.761,118.306 v1(45.2,118.745)
  Bottom Layer w0.127: v1(45.2,118.745) 46.29,118.745 R301.2@46.482,118.68
PA9: CN5.42 R60.2 R294.2 U5.F12 | length 45.3
  Top Layer w0.1: U5.F12@85.2,131.2 v2(85.6,130.8) ; R60.2@112.464,127.635 v4(113.03,127.635) ; CN5.42@120.972,126.365 121.207,126.6 122.771,126.6 123,126.371 v1(123,126.6)
  Signal Layer 2 w0.1: v2(85.6,130.8) 86,130.4 86,129.7 86.1,129.6 86.6,129.6 86.8,129.4 86.8,128.973 88.138,127.635 89.035,127.635 89.8,128.4 92.2,128.4 92.965,127.635 v4(113.03,127.635) 113.565,127.1 122.5,127.1 v1(123,126.6)
  Bottom Layer w0.127: R294.2@121.92,126.176 122.076,126.176 122.5,126.6 v1(123,126.6)
PA10: CN5.40 R58.2 R288.2 U5.E13 | length 42.5
  Top Layer w0.1: U5.E13@86,130.4 v2(86.4,130) ; CN5.40@120.972,127.635 v1(122.994,127.635)
  Top Layer w0.127: R58.2@112.464,128.905 112.776,128.905 v4(113.03,128.651)
  Signal Layer 2 w0.1: v2(86.4,130) 86.6,130 87,129.6 87.4,129.6 88.2,128.8 92.5,128.8 93.284,128.016 112.395,128.016 112.649,128.27 113.03,128.27 ; v4(113.03,128.651) 113.03,128.27 ; v1(122.994,127.635) 120.465,127.635 119.83,128.27 113.03,128.27
  Bottom Layer w0.127: R288.2@121.92,127.57 122.929,127.57 v1(122.994,127.635)
PA11: CN5.43 R63.2 U5.C15 | length 34.9
  Top Layer w0.155: U5.C15@87.6,128.8 87.6,126.141 90.297,123.444 92.837,123.444 v1(93.091,123.19) ; R63.2@112.464,125.095 112.464,125.22 112.814,125.57 113.317,125.57 v1(113.538,125.349) 113.728,125.539 114.3,125.539 114.745,125.095 CN5.43@115.872,125.095
  Signal Layer 2 w0.13: v1(93.091,123.19) 93.345,123.444 108.013,123.444 110.109,125.539 113.347,125.539 v1(113.538,125.349)
PA12: CN5.41 R61.2 U5.C14 | length 35
  Top Layer w0.1: U5.C14@87.6,129.6 88,129.2 88,128.397
  Top Layer w0.155: 88,128.397 88,126.312 90.487,123.825 92.964,123.825 v1(93.091,123.952) ; R61.2@112.464,126.365 112.908,125.92 113.347,125.92 v1(113.538,126.111) 113.728,125.92 114.3,125.92 114.745,126.365 CN5.41@115.872,126.365
  Signal Layer 2 w0.13: v1(93.091,123.952) 93.218,123.825 107.823,123.825 109.918,125.92 113.347,125.92 v1(113.538,126.111)
PA13: CN5.38 R57.2 U5.E12 | length 44.5
  Top Layer w0.1: U5.E12@86,131.2 v2(86.4,130.8) ; CN5.38@120.972,128.905 v1(122.994,128.905)
  Top Layer w0.127: v1(122.994,128.905) 124.015,128.905 124.206,128.714 126.301,128.714 126.619,129.032 R57.2@127.062,129.032
  Signal Layer 2 w0.1: v2(86.4,130.8) 86.8,130.4 89,130.4 89.2,130.2 89.2,129.8 89.4,129.6 120.2,129.6 120.895,128.905 v1(122.994,128.905)
PA14: CN5.37 R59.2 U5.B13 | length 42.7
  Top Layer w0.1: U5.B13@88.4,130.4 v2(88.8,130) ; v1(113.85,128.905) CN5.37@115.872,128.905
  Top Layer w0.127: v1(123.825,128.27) 124.46,127.635 R59.2@127.062,127.635
  Signal Layer 2 w0.1: v2(88.8,130) 88.8,129.8 89.325,129.275 92.594,129.275 93.472,128.397 111.517,128.397 112.395,129.275 113.48,129.275 v1(113.85,128.905)
  Signal Layer 2 w0.127: v1(113.85,128.905) 120.095,128.905 120.73,128.27 v1(123.825,128.27)
PA15: CN5.36 R53.2 U5.C12 | length 42.6
  Top Layer w0.1: U5.C12@87.6,131.2 v2(88,130.8) ; CN5.36@120.972,130.175 v1(122.994,130.175)
  Top Layer w0.127: v1(122.994,130.175) 123.888,130.175 124.206,129.857 125.984,129.857 126.555,130.429 R53.2@127.062,130.429
  Signal Layer 2 w0.1: v2(88,130.8) 88.1,130.7 89.18,130.7 89.451,130.429 113.284,130.429 113.665,130.81 120.523,130.81 121.158,130.175 v1(122.994,130.175)
PB0: CN6.28 JP10.1 R271.2 U5.P6 | length 49.3
  Top Layer w0.1: CN6.28@52.393,135.255 v1(54.4,135.255) 55.045,135.9 67.16,135.9 67.8,135.26 67.8,134.7 68.1,134.4 72.932,134.4 74.932,136.4 78.4,136.4 U5.P6@78.8,136
  Signal Layer 2 w0.127: JP10.1@38.862,141.478 41.91,138.43 41.91,136.525 43.688,134.747 53.892,134.747 v1(54.4,135.255)
  Bottom Layer w0.127: v1(54.4,135.255) R271.2@55.43,135.255
PB1: CN6.43 R296.2 U5.L7 | length 43.5
  Top Layer w0.1: v1(45.2,125.095) CN6.43@47.293,125.095 ; v2(80.8,135.6) U5.L7@81.2,135.2
  Signal Layer 2 w0.1: v1(45.2,125.095) 49.403,125.095 50.038,125.73 54.8,125.73 61.4,132.329 65.179,132.329 68.168,135.319 77.342,135.319 77.66,135 80.2,135 v2(80.8,135.6)
  Bottom Layer w0.1: v1(45.2,125.095) R296.2@45.778,125.095
PB2: CN6.32 R283.2 U5.R6 | length 41.4
  Top Layer w0.1: CN6.32@52.393,132.715 v1(54.4,132.715) 55.035,132.08 58.144,132.08 59.264,133.2 71.193,133.2 72,134.007 73.047,134.007 75.04,136 U5.R6@78,136
  Signal Layer 2 w0.1: v1(42.037,130.81) 46.736,130.81 48.641,132.715 v1(54.4,132.715)
  Bottom Layer w0.1: R283.2@41.402,130.498 41.725,130.498 v1(42.037,130.81)
PB3: CN5.16 R32.2 U5.C6 | length 42.1
  Top Layer w0.1: U5.C6@87.6,136 v2(88,136.4) ; CN5.16@120.972,142.875 v1(122.994,142.875)
  Top Layer w0.127: v1(122.994,142.875) R32.2@124.268,142.875
  Signal Layer 2 w0.1: v2(88,136.4) 90.3,136.4 90.679,136.779 93.599,136.779 94.12,137.3 106.7,137.3 112.9,143.5 122.369,143.5 v1(122.994,142.875)
PB4: CN5.14 JP8.2 U5.B5 | length 57.1
  Top Layer w0.1: U5.B5@88.4,136.8 88.7,137.1 92.777,137.1 v2(93.218,137.541) ; CN5.14@120.972,144.145 v1(122.994,144.145)
  Top Layer w0.127: v1(122.994,144.145) 123.375,143.764 130.302,143.764 131.953,142.113 137.033,142.113 JP8.2@138.43,143.51
  Signal Layer 2 w0.1: v2(93.218,137.541) 93.577,137.9 106.3,137.9 113.2,144.8 119.3,144.8 119.955,144.145 v1(122.994,144.145)
PB5: CN6.46 JP16.2 JP18.1 U5.E7 | length 70.5
  Top Layer w0.1: CN6.46@52.393,123.825 v1(54.4,123.825) ; U5.E7@86,135.2 v2(86.4,135.6)
  Signal Layer 2 w0.1: v1(54.4,123.825) 58.425,123.825 68.407,133.807 68.712,134.112 77.724,134.112 78.212,134.6 80.845,134.6 81.445,135.2 86,135.2 v2(86.4,135.6)
  Signal Layer 2 w0.127: JP18.1@27.432,124.206 30.226,127 34.544,127 JP16.2@35.814,128.27 38.735,128.27 43.815,123.19 53.765,123.19 v1(54.4,123.825)
PB6: CN4.7 CN6.17 R33.2 U5.A4 | length 78
  Top Layer w0.1: v1(45.2,141.605) CN6.17@47.293,141.605 ; U5.A4@89.2,137.6 v2(89.6,138)
  Top Layer w0.127: v1(45.2,141.605) R33.2@44.392,141.605 44.392,155.675 46.075,157.358 46.075,158.775 51.125,163.825 52.065,163.825 CN4.7@53.34,165.1
  Signal Layer 2 w0.1: v1(45.2,141.605) 52.9,141.605 53.4,141.105 55.11,141.105 56.205,142.2 66.588,142.2 68.072,140.716 v6(72.898,140.716)
  Signal Layer 4 w0.1: v6(72.898,140.716) 75.214,138.4 89.2,138.4 v2(89.6,138)
PB7: CN5.13 R29.2 R238.2 U5.D6 | length 34.5
  Top Layer w0.1: U5.D6@86.8,136 v2(87.2,136.4) ; v1(113.85,144.145) CN5.13@115.872,144.145
  Top Layer w0.127: R29.2@112.464,144.145 v1(113.85,144.145)
  Signal Layer 2 w0.1: v2(87.2,136.4) 87.6,136.8 90.2,136.8 90.56,137.16 93.599,137.16 94.039,137.6 106.5,137.6 113.045,144.145 v1(113.85,144.145)
  Bottom Layer w0.127: R238.2@113.222,144.145 v1(113.85,144.145)
PB8: CN5.11 R110.1 R120.2 U5.B4 | length 32.9
  Top Layer w0.1: U5.B4@88.4,137.6 88.7,137.3 92.342,137.3 v2(92.583,137.541) ; v1(113.85,145.415) CN5.11@115.872,145.415
  Signal Layer 2 w0.1: v2(92.583,137.541) 93.242,138.2 105.885,138.2 113.1,145.415 v1(113.85,145.415)
  Bottom Layer w0.1: v1(113.85,145.415) R110.1@114.85,145.415
  Bottom Layer w0.127: R120.2@112.9,145.5 112.985,145.415 v1(113.85,145.415)
PB9: CN5.9 R104.2 R233.1 U5.A3 | length 33.1
  Top Layer w0.1: U5.A3@89.2,138.4 91,138.4 v2(91.4,138) ; v1(113.85,146.685) CN5.9@115.872,146.685
  Signal Layer 2 w0.1: v2(91.4,138) 91.4,138.644 93.472,140.716 106.807,140.716 112.776,146.685 v1(113.85,146.685)
  Bottom Layer w0.1: R233.1@112.606,146.7 113.835,146.7 v1(113.85,146.685) 114.835,146.685 R104.2@114.85,146.7
PB10: CN6.42 R292.2 U5.R13 | length 46.7
  Top Layer w0.1: CN6.42@52.393,126.365 v1(54.4,126.365) 56.642,126.365 59.182,123.825 60.198,123.825 60.706,124.333 60.706,129.794 60.96,130.048 61.722,130.048 61.849,129.921 61.849,123.825 62.357,123.317 76.962,123.317 77.343,123.698 77.343,128.27 76.835,128.778 76.835,129.535 77.7,130.4 U5.R13@78,130.4
  Bottom Layer w0.1: R292.2@53.536,126.365 v1(54.4,126.365)
PB11: CN6.44 R295.2 U5.P13 | length 35.4
  Top Layer w0.1: CN6.44@52.393,125.095 v1(54.4,125.095) 57.404,125.095 59.563,122.936 77.089,122.936 77.724,123.571 77.724,128.397 77.225,128.896 77.225,129.425 77.8,130 78.4,130 U5.P13@78.8,130.4
  Bottom Layer w0.1: R295.2@53.536,125.095 v1(54.4,125.095)
PB12: CN6.52 JP19.2 U5.N14 | length 58.2
  Top Layer w0.1: CN6.52@52.393,120.015 v1(54.4,120.015) 56.415,120.015 58.955,122.555 77.724,122.555 79.629,124.46 79.629,127.889 79.2,128.318 79.2,129.2 U5.N14@79.6,129.6
  Signal Layer 2 w0.127: JP19.2@33.274,121.666 34.798,123.19 37.592,123.19 41.402,119.38 53.213,119.38 53.848,120.015 v1(54.4,120.015)
PB13: CN6.58 R314.2 R316.2 U5.M13 | length 42.1
  Top Layer w0.1: CN6.58@52.393,116.205 v1(54.4,116.205) 59.607,121.412 81.026,121.412 81.534,121.92 81.534,124.714 80.899,125.349 80.899,128.524 80.7,128.723 80.7,130.1 U5.M13@80.4,130.4
  Bottom Layer w0.1: R316.2@53.536,116.205 v1(54.4,116.205)
  Bottom Layer w0.127: v1(54.4,116.205) R314.2@55.18,116.205
PB14: CN6.54 JP21.2 R304.2 U5.M14 | length 57.2
  Top Layer w0.1: CN6.54@52.393,118.745 v1(54.4,118.745) 55.745,118.745 59.174,122.174 80.518,122.174 80.772,122.428 80.772,124.206 80.391,124.587 80.391,128.233 80.1,128.524 80.1,129.3 U5.M14@80.4,129.6
  Signal Layer 2 w0.127: JP21.2@35.814,118.364 44.323,118.364 44.577,118.11 53.34,118.11 53.975,118.745 v1(54.4,118.745)
  Bottom Layer w0.127: v1(54.4,118.745) R304.2@55.18,118.745
PB15: CN6.56 JP20.2 R309.2 U5.M15 | length 63.7
  Top Layer w0.1: CN6.56@52.393,117.475 v1(54.4,117.475) 55.075,117.475 59.393,121.793 80.772,121.793 81.153,122.174 81.153,124.333 80.645,124.841 80.645,128.397 80.4,128.642 U5.M15@80.4,128.8
  Signal Layer 2 w0.127: JP20.2@29.972,118.364 31.16,117.176 44.465,117.176 44.8,116.84 48.768,116.84 48.895,116.967 53.594,116.967 54.102,117.475 v1(54.4,117.475)
  Bottom Layer w0.127: v1(54.4,117.475) R309.2@55.18,117.475
PC0: CN6.20 R246.2 R253.2 R255.2 U5.L3 | length 34.3
  Top Layer w0.1: CN6.20@52.393,140.335 v1(54.4,140.335) ; v2(80.8,138.8) U5.L3@81.2,138.4
  Signal Layer 2 w0.1: v1(54.4,140.335) 55.435,139.3 68.15,139.3 68.75,139.9 76.4,139.9 76.9,140.4 79.564,140.4 80.8,139.164 v2(80.8,138.8)
  Bottom Layer w0.127: R255.2@53.536,140.335 v1(54.4,140.335) R253.2@55.18,140.335 ; R246.2@55.18,141.986 R253.2@55.18,140.335 ; R253.2@55.434,140.335 R253.2@55.18,140.335
PC1: CN6.1 R209.2 R210.2 R216.2 U5.M2 | length 50.7
  Top Layer w0.1: v1(45.2,151.765) CN6.1@47.293,151.765 ; v11(78.486,141.605) 78.613,141.605 80,140.218 80,139.6 U5.M2@80.4,139.2
  Signal Layer 2 w0.1: v1(45.2,151.765) 47.625,151.765 49.276,150.114 53.213,150.114 54.102,151.003 54.737,151.003 58.547,147.193 77.089,147.193 79.756,144.526 79.756,142.875 v11(78.486,141.605)
  Bottom Layer w0.1: R210.2@43.496,152.908 R209.2@43.496,154.178
  Bottom Layer w0.127: R210.2@43.496,152.908 44.392,152.012 R216.2@44.392,151.765 v1(45.2,151.765)
PC2: CN6.15 R245.2 U5.J5 | length 64.3
  Top Layer w0.1: v1(45.2,142.875) CN6.15@47.293,142.875 ; v2(82.4,137.2) U5.J5@82.8,136.8
  Signal Layer 2 w0.1: v1(45.2,142.875) 43.307,144.768 43.307,152.4 44.407,153.5 54.399,153.5 59.182,148.717 77.597,148.717 82.8,143.514 82.8,137.6 v2(82.4,137.2)
  Bottom Layer w0.127: R245.2@44.392,142.875 v1(45.2,142.875)
PC2_C: CN6.2 U5.N1 | length 33.2
  Top Layer w0.1: CN6.2@53.34,151.765 CN6.2@52.393,151.765 53.975,151.765 59.055,146.685 66.015,146.685 69.5,143.2 73.335,143.2 75.311,141.224 78.603,141.224 79.6,140.227 U5.N1@79.6,140
PC3: CN6.23 R261.2 U5.N3 | length 42.8
  Top Layer w0.1: v1(45.2,137.795) CN6.23@47.293,137.795 ; v2(79.2,138.8) U5.N3@79.6,138.4
  Signal Layer 2 w0.1: v1(45.2,137.795) 49.657,137.795 50.165,138.303 50.546,138.303 51.308,137.541 52.07,137.541 52.324,137.795 52.324,140.208 52.578,140.462 53.34,140.462 53.721,140.081 53.721,138.651 53.975,138.397 58.514,138.397 58.717,138.6 68.5,138.6 69.092,139.192 78.808,139.192 v2(79.2,138.8)
  Bottom Layer w0.127: R261.2@44.392,137.795 v1(45.2,137.795)
PC3_C: CN6.4 R219.2 U5.N2 | length 32.7
  Top Layer w0.1: CN6.4@52.393,150.495 v1(54.4,150.495) 58.591,146.304 65.896,146.304 69.4,142.8 73.1,142.8 75.057,140.843 78.557,140.843 79.2,140.2 79.2,139.6 U5.N2@79.6,139.2
  Bottom Layer w0.127: v1@54.7,150.495 R219.2@55.18,150.495
PC4: CN6.33 R50.2 R277.2 R281.2 U5.M6 | length 42.9
  Top Layer w0.1: v1(45.2,131.445) CN6.33@47.293,131.445 ; v2(80,136.4) U5.M6@80.4,136
  Top Layer w0.127: R50.2@44.388,131.572 45.073,131.572 v1(45.2,131.445)
  Signal Layer 2 w0.1: v1(45.2,131.445) 47.082,133.327 47.359,133.604 56.604,133.604 59.8,136.8 79.6,136.8 v2(80,136.4)
  Bottom Layer w0.127: R281.2@44.323,131.445 R281.2@44.392,131.445 ; R281.2@44.642,131.445 v1(45.2,131.445) 45.2,131.941 45.401,132.142 R277.2@46.228,132.142
PC5: CN6.35 R55.2 R282.2 R286.2 U5.N6 | length 42.4
  Top Layer w0.1: v1(45.2,130.175) CN6.35@47.293,130.175 ; v2(79.2,136.4) U5.N6@79.6,136
  Top Layer w0.127: R55.2@44.388,130.175 v1(45.2,130.175)
  Signal Layer 2 w0.1: v1(45.2,130.175) 47.371,130.175 49.276,132.08 55.78,132.08 57.242,133.542 60.1,136.4 v2(79.2,136.4)
  Bottom Layer w0.1: v1(45.2,130.175) 45.2,129.806 45.531,129.475 R282.2@46.228,129.475
  Bottom Layer w0.127: R286.2@44.392,130.175 v1(45.2,130.175)
PC6: CN13.6 JP32.2 U5.F14 | length 50.3
  Top Layer w0.1: CN13.6@110.992,109.855 v1(112.881,109.855)
  Top Layer w0.127: U5.F14@85.2,129.6 85.6,129.2 85.6,112.6 JP32.2@86,112.2
  Signal Layer 2 w0.102: JP32.2@86,112.2 88.608,114.808 103.505,114.808 v1(104.013,114.3)
  Bottom Layer w0.127: v1(104.013,114.3) 104.013,113.771 108.393,109.391 111.291,109.391 111.755,109.855 v1(112.881,109.855)
PC7: CN13.24 JP35.2 R113.2 U5.E15 | length 119.1
  Top Layer w0.102: R113.2@114.612,97.155 R113.2@114.612,97.091 ; JP35.2@134.747,89.916 134.663,90 130.091,90 128.524,91.567 122.999,97.092 116.992,97.092 116.3,96.4 115,96.4 114.612,96.788 R113.2@114.612,97.091 ; v1(112.871,98.425) CN13.24@110.992,98.425 v1(112.871,98.425) ; v1(112.871,98.425) 114.205,97.091 R113.2@114.612,97.091
  Top Layer w0.127: U5.E15@86,128.8 86,119.232 ; 86,119.232 88.392,116.84 ; 86,119.232 88.392,116.84 ; 88.392,116.84 v1(96.647,116.84) 88.392,116.84
  Bottom Layer w0.127: v1(96.647,116.84) 96.52,116.713 96.52,116.459 96.647,116.332 97.155,116.332 97.282,116.205 97.282,115.951 97.155,115.824 96.647,115.824 96.52,115.697 96.52,115.443 96.647,115.316 97.155,115.316 97.282,115.189 97.282,114.935 97.155,114.808 96.647,114.808 96.52,114.681 96.52,114.427 96.647,114.3 97.155,114.3 97.282,114.173 97.282,113.919 97.155,113.792 96.647,113.792 96.52,113.665 96.52,105.156 ; 96.52,105.156 103.949,97.727 ; 96.52,105.156 103.949,97.726 ; 103.949,97.726 105.156,97.726 ; 103.949,97.727 105.156,97.727 ; 105.156,97.727 105.283,97.854 ; 105.156,97.726 105.283,97.853 ; 105.283,97.854 105.283,98.298 ; 105.283,98.298 105.41,98.425 ; 105.283,98.298 105.41,98.425 ; 105.41,98.425 105.664,98.425 ; 105.41,98.425 105.664,98.425 ; 105.664,98.425 105.791,98.298 ; 105.664,98.425 105.791,98.298 ; 105.791,97.821 105.791,98.298 ; 105.791,97.821 105.886,97.727 ; 105.791,97.821 105.886,97.726 ; 105.886,97.726 106.17,97.726 ; 105.886,97.727 106.17,97.727 ; 106.17,97.727 106.299,97.856 ; 106.17,97.726 106.299,97.856 ; 106.299,97.856 106.299,98.298 ; 106.299,98.298 106.426,98.425 ; 106.299,98.298 106.426,98.425 ; 106.426,98.425 v1(112.871,98.425) 106.426,98.425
